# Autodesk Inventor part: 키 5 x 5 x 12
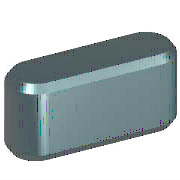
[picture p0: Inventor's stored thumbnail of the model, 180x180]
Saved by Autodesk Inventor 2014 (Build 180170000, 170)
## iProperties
Created: 2012-02
Part Number: 키 5 x 5 x 12
Material: 강철, 연강
Description: 키 및 해당 키홈
Document SubType Name: Modeling
Standard: KS B 1311
Designer: mduedu
Standards Organization: KS
Language: ko-KR
Size Designation: 5 x 5 x 12
Categories: <MemberInstance><Categories><Category DisplayName="샤프트 부품" InternalName="7f7aeb1f-a693-4053-b835-cee3144e0d98" Mnemonic="SHFT"><Category DisplayName="키" Interna
Density: 1 g/cm^3
Appearance: 노란색
IsCustomPart: 1
Author: mduedu
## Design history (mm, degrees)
workplane "Work Plane1"
workplane "Work Plane2"
sketch "스케치1"
  geometry: L1 (2.5, 2.5)-(9.5, 2.5); L2 (9.5, -2.5)-(2.5, -2.5); L3 (0, 9.4)-(0, -7.4) reference; L4 (-5, 0)-(30, 0) reference; L5 (12, 0)-(12, 7); A1 r 2.5 centre (2.5, 0) between (2.5, 2.5) and (2.5, -2.5); A2 r 2.5 centre (9.5, 0) between (9.5, -2.5) and (9.5, 2.5)
  constraints: 6 end point, 5 point on circle, 4 tangent, 3 point on line, 2 centre point, 1 horizontal, 1 parallel, 1 perpendicular
  dimensions: "d0" = 2.5 radius of A1 (= 0.5 x PB); "d13" = 2.5 radius of A2 (= 0.5 x PB); "d14" = 12 distance between parallel lines of L5 L3 (= NLG)
extrude "본체1" new body sketch "스케치1" taper "d3" = 0 deg; stored distance "d4" = 10
workplane "Work Plane3"
body "Solid1"
chamfer "모따기1" distance "d8" = 0.4 (= PHH); stored, may be unused: second distance "d9" = 0.4 (= PHH), angle "d15" = 45 deg
other parameters: "d1" = -3 (= -PNT), "d2" = 2 (= PH - PNT), "NLG" = 12 [user parameter; used in 3 equation terms], "PB" = 5 [user parameter; used in 2 equation terms], "PNT" = 3 [user parameter; used in 2 equation terms], "PH" = 5 [user parameter; used in 1 equation term], "PHH" = 0.4 [user parameter; used in 2 equation terms], "d10" = 0, "d16" = 0, "d17" = 0, "d18" = 0, "WDMIN" = 12 [user parameter], "PLB2" = 12 (= NLG) [user parameter], "WDMAX" = 17 [user parameter], "PLB1" = 12 (= NLG) [user parameter], "RR" = 0.16 [user parameter], "PUEB" = 2.3 [user parameter]
